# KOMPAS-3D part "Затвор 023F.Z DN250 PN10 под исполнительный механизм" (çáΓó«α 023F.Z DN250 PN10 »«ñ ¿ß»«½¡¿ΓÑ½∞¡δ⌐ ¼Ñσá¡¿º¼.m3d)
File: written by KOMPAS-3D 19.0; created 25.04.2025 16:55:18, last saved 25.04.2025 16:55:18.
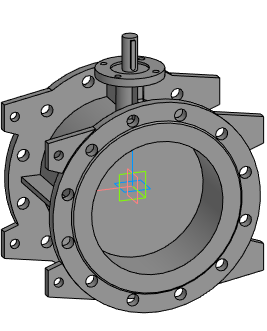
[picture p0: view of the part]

Document properties: Автор: Евгений; Полное имя файла: E:\Dendor Работа Сачек\3D для проекитирвщиков\1.7 Тип 023F.Z Затвор дисковый поворотный фланцевый с двумя эксцентриками\stp_Тип 023F.Z. Затвор под исполн. механизм\Затвор 023F.Z DN250 PN10 под исполнительный механизм.m3d

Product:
- Part/product: Затвор 023F.Z DN250 PN10 под исполнительный механизм

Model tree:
1. Операция без истории:1  (labels: Затвор 023F.Z DN250 PN10 под исполнительный механизм)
